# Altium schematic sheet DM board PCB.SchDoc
size 386 x 246 mm
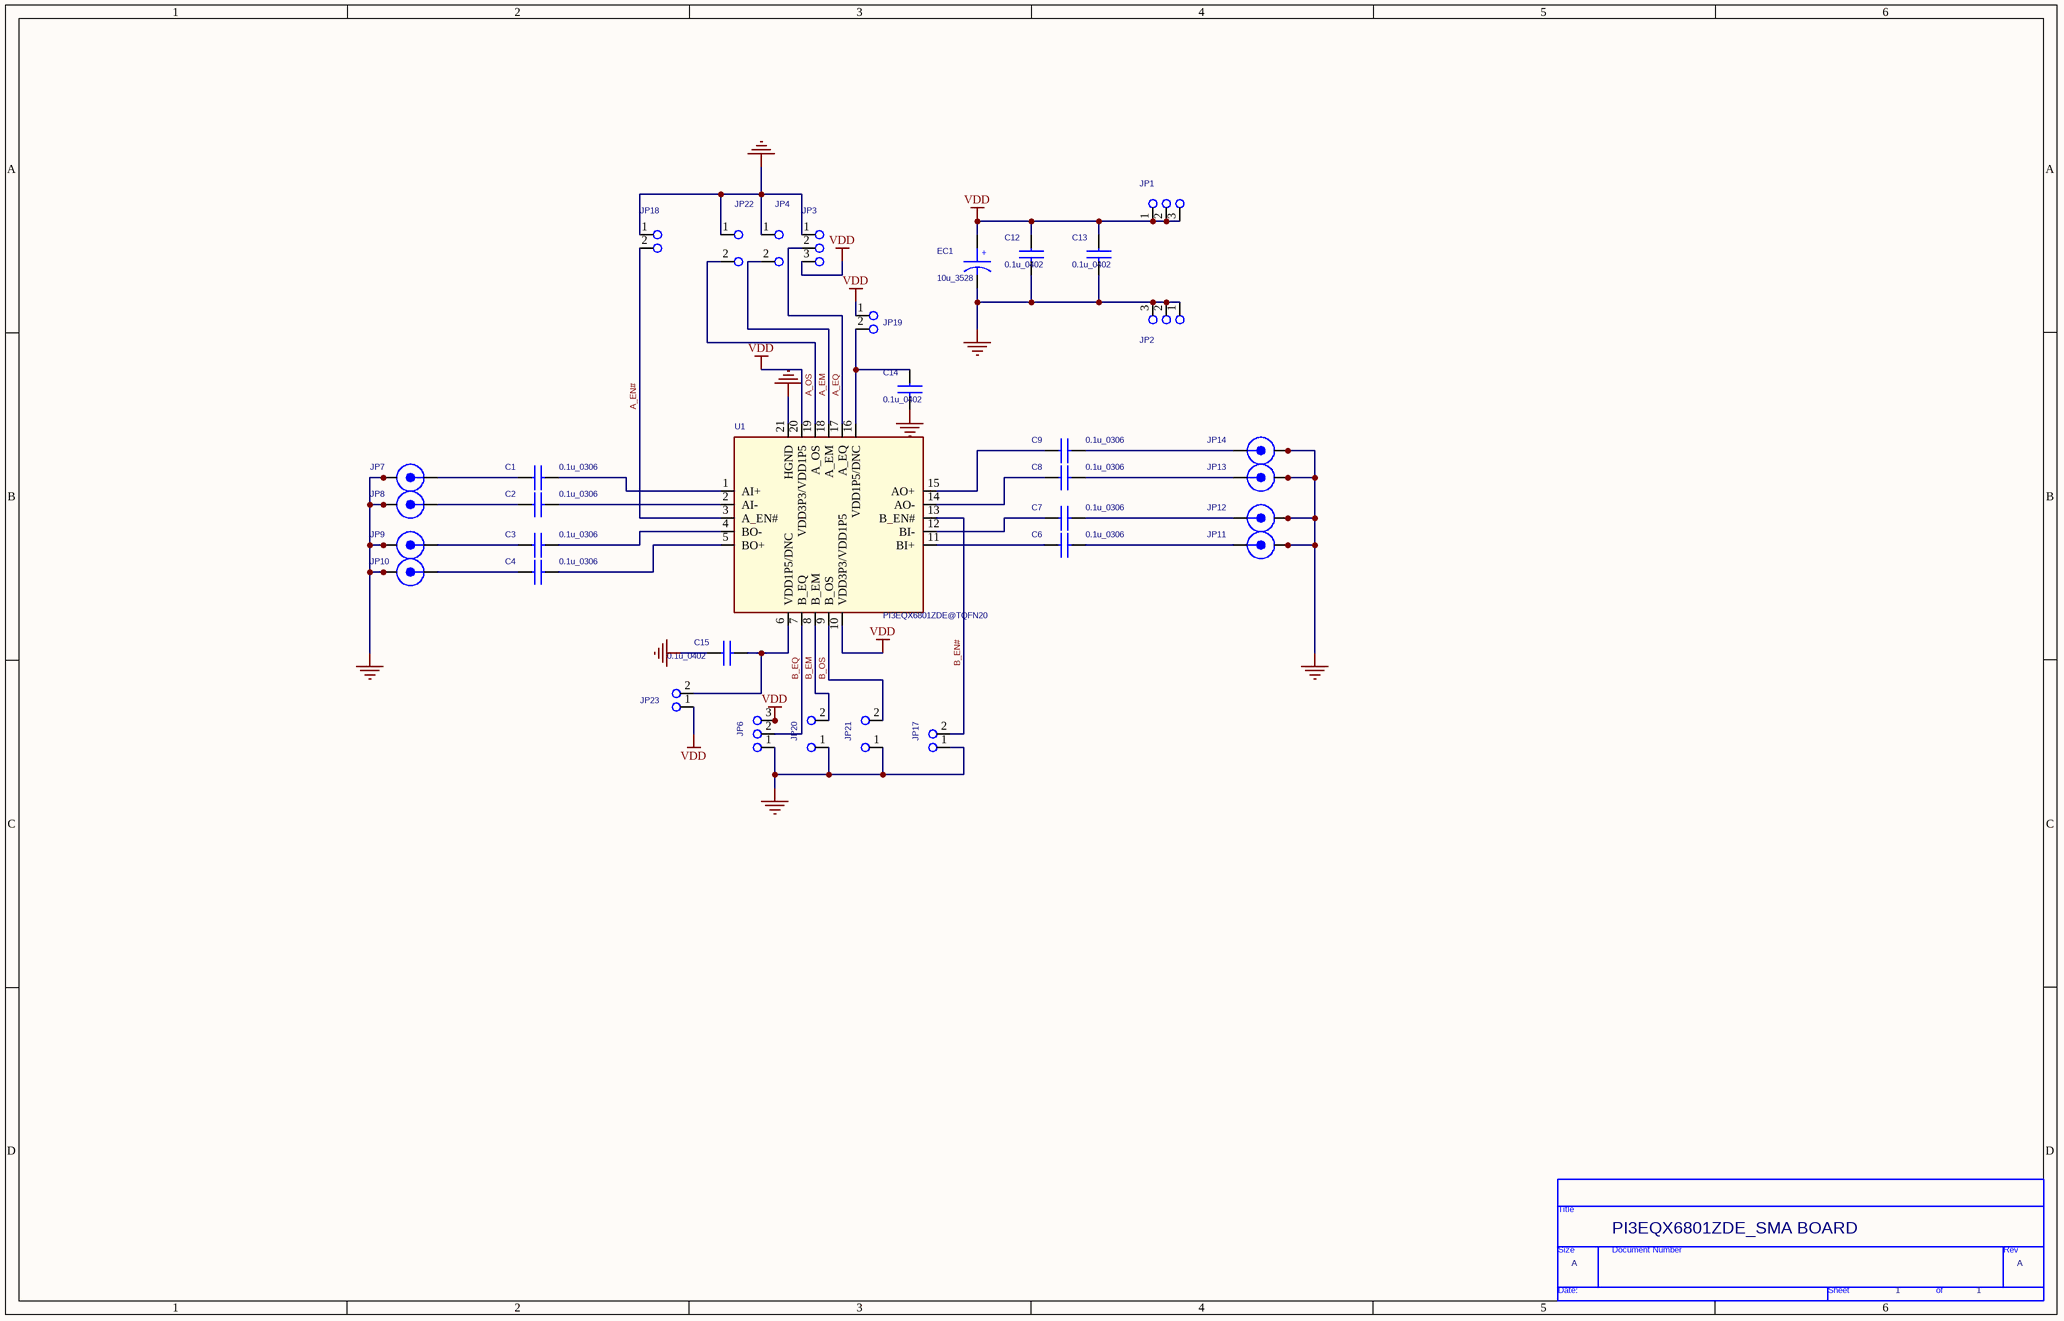
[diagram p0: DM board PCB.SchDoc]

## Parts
*  RevCode: A  Title: PI3EQX6801ZDE_SMA BOARD  Page Number: 1  (hidden comment: TitleBlock0)  (graphical)
C1  0.1u_0306  [CC_0306]
C2  0.1u_0306  [CC_0306]
C3  0.1u_0306  [CC_0306]
C4  0.1u_0306  [CC_0306]
C6  0.1u_0306  [CC_0306]
C7  0.1u_0306  [CC_0306]
C8  0.1u_0306  [CC_0306]
C9  0.1u_0306  [CC_0306]
C12  0.1u_0402  [CC_0402]
C13  0.1u_0402  [CC_0402]
C14  0.1u_0402  [CC_0402]
C15  0.1u_0402  [CC_0402]
EC1  10u_3528  [CT_3528]
JP1  3x1 Pin Header  [3x1 Pin Header]  (value not drawn)
JP2  3x1 Pin Header  [3x1 Pin Header]  (value not drawn)
JP3  3x1 Pin Header  [3x1 Pin Header]  (value not drawn)
JP4  2x1_200 mil Pin Header  [2x1_200 mil Pin Header]  (value not drawn)
JP6  3x1 Pin Header  [3x1 Pin Header]  (value not drawn)
JP7  RF_SMA_End  [RF_SMA_End]  (value not drawn)
JP8  RF_SMA_End  [RF_SMA_End]  (value not drawn)
JP9  RF_SMA_End  [RF_SMA_End]  (value not drawn)
JP10  RF_SMA_End  [RF_SMA_End]  (value not drawn)
JP11  RF_SMA_End  [RF_SMA_End]  (value not drawn)
JP12  RF_SMA_End  [RF_SMA_End]  (value not drawn)
JP13  RF_SMA_End  [RF_SMA_End]  (value not drawn)
JP14  RF_SMA_End  [RF_SMA_End]  (value not drawn)
JP17  2x1 Pin Header  [2x1 Pin Header]  (value not drawn)
JP18  2x1 Pin Header  [2x1 Pin Header]  (value not drawn)
JP19  2x1 Pin Header  [2x1 Pin Header]  (value not drawn)
JP20  2x1_200 mil Pin Header  [2x1_200 mil Pin Header]  (value not drawn)
JP21  2x1_200 mil Pin Header  [2x1_200 mil Pin Header]  (value not drawn)
JP22  2x1_200 mil Pin Header  [2x1_200 mil Pin Header]  (value not drawn)
JP23  2x1 Pin Header  [2x1 Pin Header]  (value not drawn)
U1  PI3EQX6801ZDE@TQFN20  [TQFN20_4x4 SOCKET]

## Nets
GND: C12.2 C13.2 C14.2 C15.1 EC1.2 JP2.1 JP2.2 JP2.3 JP3.1 JP4.1 JP6.1 JP7.2 JP7.3 JP7.4 JP7.5 JP7.6 JP7.7 JP7.8 JP7.9 JP7.10 JP7.11 JP7.12 JP7.13 JP7.14 JP7.15 JP7.16 JP7.17 JP7.18 JP7.19 JP7.20 JP7.21 JP7.22 JP7.23 JP7.24 JP7.25 JP7.26 JP7.27 JP7.28 JP7.29 JP7.30 JP7.31 JP7.32 JP7.33 JP7.34 JP8.2 JP8.3 JP8.4 JP8.5 JP8.6 JP8.7 JP8.8 JP8.9 JP8.10 JP8.11 JP8.12 JP8.13 JP8.14 JP8.15 JP8.16 JP8.17 JP8.18 JP8.19 JP8.20 JP8.21 JP8.22 JP8.23 JP8.24 JP8.25 JP8.26 JP8.27 JP8.28 JP8.29 JP8.30 JP8.31 JP8.32 JP8.33 JP8.34 JP9.2 JP9.3 JP9.4 JP9.5 JP9.6 JP9.7 JP9.8 JP9.9 JP9.10 JP9.11 JP9.12 JP9.13 JP9.14 JP9.15 JP9.16 JP9.17 JP9.18 JP9.19 JP9.20 JP9.21 JP9.22 JP9.23 JP9.24 JP9.25 JP9.26 JP9.27 JP9.28 JP9.29 JP9.30 JP9.31 JP9.32 JP9.33 JP9.34 JP10.2 JP10.3 JP10.4 JP10.5 JP10.6 JP10.7 JP10.8 JP10.9 JP10.10 JP10.11 JP10.12 JP10.13 JP10.14 JP10.15 JP10.16 JP10.17 JP10.18 JP10.19 JP10.20 JP10.21 JP10.22 JP10.23 JP10.24 JP10.25 JP10.26 JP10.27 JP10.28 JP10.29 JP10.30 JP10.31 JP10.32 JP10.33 JP10.34 JP11.2 JP11.3 JP11.4 JP11.5 JP11.6 JP11.7 JP11.8 JP11.9 JP11.10 JP11.11 JP11.12 JP11.13 JP11.14 JP11.15 JP11.16 JP11.17 JP11.18 JP11.19 JP11.20 JP11.21 JP11.22 JP11.23 JP11.24 JP11.25 JP11.26 JP11.27 JP11.28 JP11.29 JP11.30 JP11.31 JP11.32 JP11.33 JP11.34 JP12.2 JP12.3 JP12.4 JP12.5 JP12.6 JP12.7 JP12.8 JP12.9 JP12.10 JP12.11 JP12.12 JP12.13 JP12.14 JP12.15 JP12.16 JP12.17 JP12.18 JP12.19 JP12.20 JP12.21 JP12.22 JP12.23 JP12.24 JP12.25 JP12.26 JP12.27 JP12.28 JP12.29 JP12.30 JP12.31 JP12.32 JP12.33 JP12.34 JP13.2 JP13.3 JP13.4 JP13.5 JP13.6 JP13.7 JP13.8 JP13.9 JP13.10 JP13.11 JP13.12 JP13.13 JP13.14 JP13.15 JP13.16 JP13.17 JP13.18 JP13.19 JP13.20 JP13.21 JP13.22 JP13.23 JP13.24 JP13.25 JP13.26 JP13.27 JP13.28 JP13.29 JP13.30 JP13.31 JP13.32 JP13.33 JP13.34 JP14.2 JP14.3 JP14.4 JP14.5 JP14.6 JP14.7 JP14.8 JP14.9 JP14.10 JP14.11 JP14.12 JP14.13 JP14.14 JP14.15 JP14.16 JP14.17 JP14.18 JP14.19 JP14.20 JP14.21 JP14.22 JP14.23 JP14.24 JP14.25 JP14.26 JP14.27 JP14.28 JP14.29 JP14.30 JP14.31 JP14.32 JP14.33 JP14.34 JP17.1 JP18.1 JP20.1 JP21.1 JP22.1 U1.21(HGND)
VDD: C12.1 C13.1 EC1.1 JP1.1 JP1.2 JP1.3 JP3.3 JP6.3 JP19.1 JP23.1 U1.10(VDD3P3/VDD1P5) U1.20(VDD3P3/VDD1P5)
A_EM: JP4.2 U1.18(A_EM)
A_EN#: JP18.2 U1.3(A_EN#)
A_EQ: JP3.2 U1.17(A_EQ)
A_OS: JP22.2 U1.19(A_OS)
B_EM: JP20.2 U1.8(B_EM)
B_EN#: JP17.2 U1.13(B_EN#)
B_EQ: JP6.2 U1.7(B_EQ)
B_OS: JP21.2 U1.9(B_OS)
NetC1_1: C1.1 JP7.1
NetC1_2: C1.2 U1.1(AI+)
NetC2_1: C2.1 JP8.1
NetC2_2: C2.2 U1.2(AI-)
NetC3_1: C3.1 JP9.1
NetC3_2: C3.2 U1.4(BO-)
NetC4_1: C4.1 JP10.1
NetC4_2: C4.2 U1.5(BO+)
NetC6_1: C6.1 U1.11(BI+)
NetC6_2: C6.2 JP11.1
NetC7_1: C7.1 U1.12(BI-)
NetC7_2: C7.2 JP12.1
NetC8_1: C8.1 U1.14(AO-)
NetC8_2: C8.2 JP13.1
NetC9_1: C9.1 U1.15(AO+)
NetC9_2: C9.2 JP14.1
NetC14_1: C14.1 JP19.2 U1.16(VDD1P5/DNC)
NetC15_2: C15.2 JP23.2 U1.6(VDD1P5/DNC)

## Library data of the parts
C1-C4 C6-C9 = C_0.1u_0306
C12-C14 = C_0.1u_0402_Dup1
C15 = C_0.1u_0402
EC1 = C_tan_22u_3528
JP1 JP2 = 3x1 Pin Header_Dup1
JP18 JP19 JP23 = 2x1 Pin Header_Dup1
